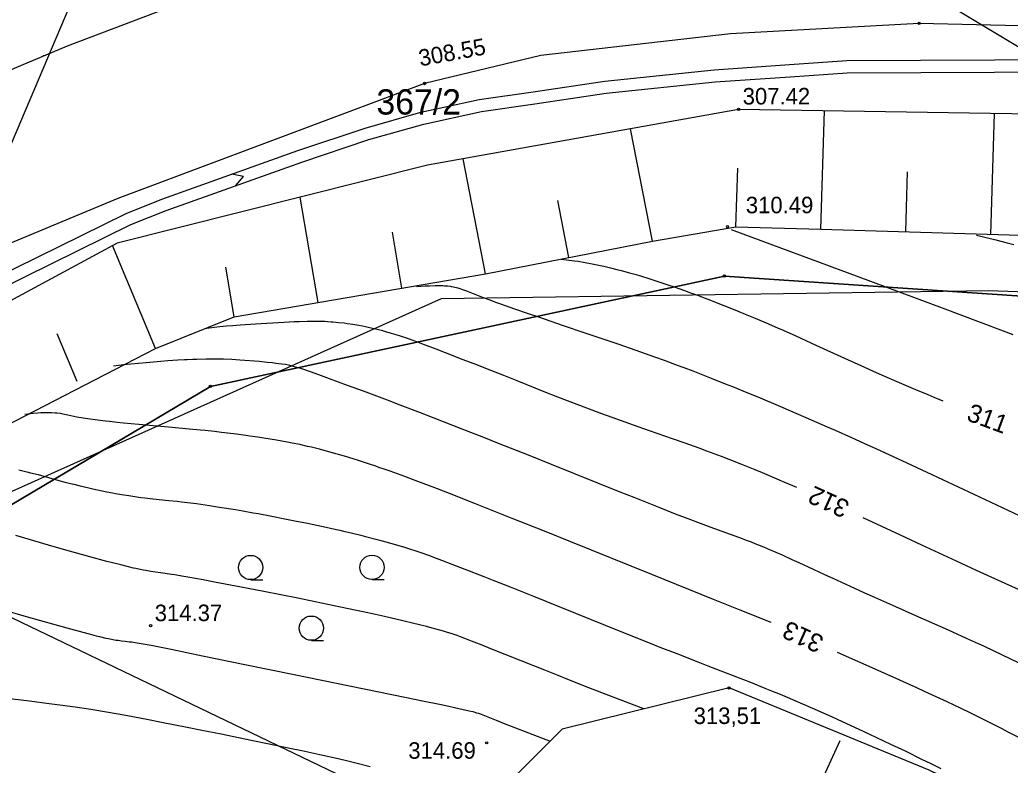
# Model space of a CAD drawing. Extents: x 7477803 to 7478145, y 5500698 to 5500984.
# Drawn here: x 7477904.37 to 7477945.16, y 5500778.77 to 5500809.46 of the extents above; entities that cross this region are included whole.
import ezdxf

# ---------------------------------------------------------------- set-up
doc = ezdxf.new("R2010")
doc.units = 0
for name, color, linetype in [('203-Punkt załamania granicy działki nie stabilizowany', 7, 'Continuous'), ('gr_dzialki', 7, 'Continuous'), ('gr_klasy', 7, 'Continuous'), ('jezdnia', 7, 'Continuous'), ('nr_dzialki', 7, 'Continuous'), ('ogr_symb', 7, 'Continuous'), ('pkt_wys', 7, 'Continuous'), ('rowy', 7, 'Continuous'), ('skarp_wypel', 7, 'Continuous'), ('skarpa_dol', 7, 'Continuous'), ('skarpa_gora', 7, 'Continuous'), ('warst_ciagla', 7, 'Continuous'), ('warst_opis', 7, 'Continuous'), ('warst_pogrub', 7, 'Continuous'), ('warst_przeryw', 7, 'Continuous'), ('zakresy', 7, 'Continuous'), ('zielen', 7, 'Continuous')]:
    doc.layers.add(name, color=color, linetype=linetype)

# ---------------------------------------------------------------- blocks, each defined once
blk = doc.blocks.new('203')
blk.add_circle((0, 0), 0.045)
blk = doc.blocks.new('801')
at = {"layer": 'pkt_wys'}
blk.add_circle((0, 0), 0.045, dxfattribs=at)
blk.add_circle((0, 0), 0.045, dxfattribs=at)
blk = doc.blocks.new('941_5')
at = {"layer": 'zielen'}
for p, q in [((-2.5, 0.46), (-2, 0.46)), ((2.5, 0.46), (3, 0.46)), ((0, -2.04), (0.5, -2.04))]:
    blk.add_line(p, q, dxfattribs=at)
for centre in [(-2.503, 0.963), (2.497, 0.963), (-0.003, -1.537)]:
    blk.add_circle(centre, 0.5, dxfattribs=at)
blk = doc.blocks.new('801_5_1')
at = {"layer": 'pkt_wys'}
blk.add_circle((0, 0), 0.05, dxfattribs=at)
blk.add_circle((0, 0), 0.05, dxfattribs=at)
blk = doc.blocks.new('801_5_3')
at = {"layer": 'pkt_wys'}
blk.add_circle((0, 0), 0.05, dxfattribs=at)
blk.add_circle((0, 0), 0.05, dxfattribs=at)

msp = doc.modelspace()

# ---------------------------------------------------------------- linework, layer by layer
at = {"layer": 'gr_dzialki'}
for points in [[(7477906.59, 5500810.42), (7477901.18, 5500797.68)], [(7477942.51, 5500810.15), (7477965.87, 5500796.14)], [(7477912.22, 5500794.37), (7477933.39, 5500798.91)], [(7477933.39, 5500798.91), (7477948.7, 5500797.88)], [(7477898.04, 5500785.95), (7477912.22, 5500794.37)]]:
    msp.add_lwpolyline(points, dxfattribs=at)
at = {"layer": 'gr_klasy'}
for points in [[(7477933.39, 5500798.91), (7477912.22, 5500794.37)], [(7477948.7, 5500797.88), (7477933.39, 5500798.91)], [(7477912.22, 5500794.37), (7477898.04, 5500785.95)]]:
    msp.add_lwpolyline(points, dxfattribs=at)
at = {"layer": 'jezdnia'}
for points in [[(7477875.926, 5500787.879), (7477876.814, 5500788.851), (7477888.353, 5500798.574), (7477893.52, 5500801.94), (7477899.965, 5500805.717), (7477906.333, 5500808.394), (7477918.837, 5500813.137), (7477925.266, 5500814.534), (7477933.655, 5500815.503), (7477941.064, 5500815.881), (7477951.515, 5500815.693), (7477966.065, 5500814.879), (7477981.427, 5500813.916), (7477996.758, 5500812.562), (7478008.149, 5500811.845)], [(7478007.787, 5500804.444), (7477996.226, 5500805.272), (7477980.454, 5500806.765), (7477965.783, 5500808.078), (7477950.842, 5500809.092), (7477941.412, 5500809.312), (7477933.642, 5500808.883), (7477925.833, 5500807.985), (7477921.044, 5500806.84), (7477908.409, 5500802.106), (7477902.302, 5500799.559), (7477897.005, 5500796.683), (7477891.579, 5500793.077), (7477886.813, 5500789.372), (7477881.349, 5500784.496), (7477881.326, 5500784.471)]]:
    msp.add_lwpolyline(points, dxfattribs=at)
at = {"layer": 'ogr_symb'}
msp.add_lwpolyline([(7477891.276, 5500779.392), (7477896.666, 5500786.743), (7477921.734, 5500797.99), (7477944.284, 5500798.315), (7477964.224, 5500797.617), (7478003.756, 5500796.28)], dxfattribs=at)
at = {"layer": 'rowy'}
for points in [[(7477903.253, 5500798.785), (7477908.747, 5500801.483), (7477910.219, 5500802.081), (7477915.822, 5500804.075), (7477918.6, 5500805.006), (7477920.886, 5500805.655), (7477923.298, 5500806.18), (7477925.514, 5500806.496), (7477928.461, 5500806.935), (7477932.972, 5500807.407), (7477936.072, 5500807.618), (7477938.432, 5500807.783), (7477947.546, 5500807.824), (7477950.631, 5500807.793), (7477969.517, 5500806.584), (7477989.191, 5500804.994), (7477997.207, 5500804.282)], [(7477882.663, 5500783.628), (7477883.714, 5500784.691), (7477887.616, 5500787.993), (7477891.069, 5500790.733), (7477893.37, 5500792.367), (7477898.157, 5500795.46), (7477901.645, 5500797.349), (7477903.482, 5500798.34), (7477908.951, 5500801.027), (7477910.397, 5500801.613), (7477915.985, 5500803.602), (7477918.748, 5500804.528), (7477921.007, 5500805.169), (7477923.387, 5500805.687), (7477925.587, 5500806.001), (7477928.524, 5500806.439), (7477933.015, 5500806.909), (7477936.106, 5500807.119), (7477938.45, 5500807.283), (7477947.545, 5500807.324), (7477950.612, 5500807.294), (7477969.481, 5500806.086), (7477989.149, 5500804.495), (7477997.163, 5500803.784)], [(7477913.272, 5500802.637), (7477913.579, 5500803.004), (7477913.105, 5500803.108)]]:
    msp.add_lwpolyline(points, dxfattribs=at)
at = {"layer": 'skarp_wypel'}
for p, q in [((7477937.366, 5500800.835), (7477937.511, 5500805.721)), ((7477944.363, 5500800.628), (7477944.51, 5500805.608)), ((7477930.426, 5500800.345), (7477929.523, 5500804.978)), ((7477923.556, 5500799.006), (7477922.633, 5500803.739)), ((7477933.868, 5500800.938), (7477933.939, 5500803.358)), ((7477940.865, 5500800.731), (7477940.938, 5500803.198)), ((7477916.657, 5500797.823), (7477915.92, 5500802.16)), ((7477926.991, 5500799.675), (7477926.535, 5500802.017)), ((7477920.107, 5500798.409), (7477919.716, 5500800.711)), ((7477909.966, 5500795.925), (7477908.188, 5500800.168)), ((7477913.206, 5500797.237), (7477912.86, 5500799.272)), ((7477906.738, 5500794.573), (7477905.915, 5500796.536)), ((7477935.1, 5500773.056), (7477938.156, 5500779.794))]:
    msp.add_line(p, q, dxfattribs=at)
at = {"layer": 'skarpa_dol'}
msp.add_lwpolyline([(7478003.179, 5500722.859), (7478004.323, 5500725.251), (7478005.298, 5500730.032), (7478003.066, 5500732.439), (7477998.881, 5500736.525), (7477989.029, 5500747.324), (7477982.233, 5500752.776), (7477973.187, 5500758.837), (7477956.935, 5500769.599), (7477950.58, 5500774.332), (7477941.825, 5500778.562), (7477933.581, 5500781.953), (7477926.713, 5500780.256), (7477921.899, 5500775.451), (7477920.234, 5500772.903)], dxfattribs=at)
at = {"layer": 'skarpa_gora'}
for points in [[(7478007.749, 5500802.055), (7477980.618, 5500803.745), (7477949.546, 5500805.521), (7477933.975, 5500805.774), (7477921.168, 5500803.47), (7477908.381, 5500800.266), (7477897.978, 5500794.654), (7477888.325, 5500787.474), (7477883.93, 5500782.828)], [(7477889.282, 5500779.695), (7477895.338, 5500786.582), (7477897.871, 5500788.956), (7477903.767, 5500792.731), (7477909.966, 5500795.925), (7477913.206, 5500797.237), (7477923.556, 5500799.006), (7477930.426, 5500800.345), (7477933.868, 5500800.938), (7477937.366, 5500800.835), (7477947.862, 5500800.525), (7477951.313, 5500800.09), (7477958.091, 5500798.34), (7477959.924, 5500797.862), (7477975.395, 5500787.769), (7477983.174, 5500779.337)]]:
    msp.add_lwpolyline(points, dxfattribs=at)
at = {"layer": 'warst_ciagla'}
for points in [[(7477905.377, 5500807.994), (7477905.336, 5500807.972)], [(7477926.665, 5500799.612), (7477927, 5500799.571), (7477927.221, 5500799.54), (7477927.368, 5500799.517), (7477927.658, 5500799.468), (7477927.872, 5500799.428), (7477928.014, 5500799.4), (7477928.294, 5500799.341), (7477928.431, 5500799.311), (7477928.703, 5500799.247), (7477928.968, 5500799.182), (7477929.142, 5500799.137), (7477929.479, 5500799.046), (7477929.754, 5500798.969), (7477929.932, 5500798.917), (7477930.279, 5500798.812), (7477930.448, 5500798.759), (7477930.78, 5500798.651), (7477931.107, 5500798.542), (7477931.322, 5500798.467), (7477931.752, 5500798.314), (7477931.995, 5500798.226), (7477932.321, 5500798.105), (7477932.485, 5500798.043), (7477932.815, 5500797.918), (7477933.259, 5500797.745), (7477933.482, 5500797.657), (7477933.99, 5500797.453), (7477934.245, 5500797.348), (7477934.588, 5500797.205), (7477934.761, 5500797.132), (7477935.107, 5500796.985), (7477935.573, 5500796.783), (7477935.808, 5500796.68), (7477936.34, 5500796.443), (7477937.156, 5500796.071), (7477938.342, 5500795.528), (7477939.007, 5500795.228), (7477939.647, 5500794.942), (7477939.981, 5500794.795), (7477940.492, 5500794.573), (7477941.265, 5500794.242), (7477941.773, 5500794.03), (7477942.022, 5500793.927), (7477942.385, 5500793.78)], [(7477936.377, 5500790.203), (7477935.882, 5500790.417), (7477935.564, 5500790.553), (7477934.955, 5500790.807), (7477934.665, 5500790.927), (7477934.111, 5500791.15), (7477933.593, 5500791.354), (7477933.268, 5500791.479), (7477932.664, 5500791.707), (7477932.351, 5500791.823), (7477931.776, 5500792.031), (7477931.254, 5500792.214), (7477930.312, 5500792.539), (7477929.641, 5500792.773), (7477928.772, 5500793.082), (7477928.349, 5500793.236), (7477927.728, 5500793.466), (7477926.927, 5500793.77), (7477926.538, 5500793.92), (7477925.968, 5500794.146), (7477924.855, 5500794.592), (7477924.301, 5500794.812), (7477923.563, 5500795.105), (7477923.193, 5500795.25), (7477922.638, 5500795.467), (7477921.898, 5500795.753), (7477921.527, 5500795.896), (7477921.033, 5500796.084), (7477920.786, 5500796.176), (7477920.417, 5500796.308), (7477920.05, 5500796.433), (7477919.867, 5500796.491), (7477919.686, 5500796.547), (7477919.444, 5500796.616), (7477919.324, 5500796.649), (7477919.085, 5500796.711), (7477918.768, 5500796.785), (7477918.61, 5500796.819), (7477918.492, 5500796.842), (7477918.335, 5500796.872), (7477918.257, 5500796.886), (7477918.082, 5500796.915), (7477917.85, 5500796.949), (7477917.734, 5500796.964), (7477917.504, 5500796.99), (7477917.402, 5500797), (7477917.266, 5500797.012), (7477917.199, 5500797.017), (7477917.047, 5500797.027), (7477916.934, 5500797.033), (7477916.783, 5500797.039), (7477916.708, 5500797.041), (7477916.539, 5500797.043), (7477916.428, 5500797.044), (7477916.206, 5500797.041), (7477915.88, 5500797.031), (7477915.668, 5500797.021), (7477915.26, 5500796.999), (7477914.076, 5500796.928), (7477913.443, 5500796.886), (7477913.151, 5500796.865), (7477912.887, 5500796.844), (7477912.741, 5500796.83), (7477912.487, 5500796.804), (7477912.173, 5500796.766), (7477911.988, 5500796.742)], [(7477935.315, 5500784.644), (7477934.996, 5500784.776), (7477934.428, 5500785.001), (7477934.043, 5500785.154), (7477932.945, 5500785.594), (7477930.408, 5500786.618), (7477927.066, 5500787.968), (7477925.988, 5500788.401), (7477924.652, 5500788.934), (7477924.027, 5500789.182), (7477923.143, 5500789.531), (7477922.065, 5500789.953), (7477921.569, 5500790.145), (7477920.657, 5500790.494), (7477920.233, 5500790.653), (7477919.624, 5500790.874), (7477919.426, 5500790.944), (7477919.165, 5500791.035), (7477919.037, 5500791.079), (7477918.781, 5500791.165), (7477918.447, 5500791.274), (7477918.282, 5500791.327), (7477917.918, 5500791.44), (7477917.739, 5500791.494), (7477917.503, 5500791.563), (7477917.387, 5500791.597), (7477917.157, 5500791.661), (7477916.857, 5500791.742), (7477916.709, 5500791.78), (7477916.382, 5500791.861), (7477916.222, 5500791.899), (7477915.905, 5500791.97), (7477915.589, 5500792.035), (7477915.377, 5500792.077), (7477914.941, 5500792.155), (7477914.422, 5500792.24), (7477914.181, 5500792.277), (7477913.851, 5500792.324), (7477913.681, 5500792.347), (7477913.29, 5500792.399), (7477912.676, 5500792.473), (7477912.393, 5500792.504), (7477912.006, 5500792.545), (7477911.809, 5500792.566), (7477911.354, 5500792.61), (7477910.65, 5500792.673), (7477909.714, 5500792.754), (7477909.268, 5500792.794), (7477908.645, 5500792.855), (7477908.386, 5500792.882), (7477908.06, 5500792.918), (7477907.905, 5500792.936), (7477907.574, 5500792.977), (7477907.172, 5500793.032), (7477906.986, 5500793.061), (7477906.723, 5500793.105), (7477906.475, 5500793.153), (7477906.355, 5500793.179), (7477906.144, 5500793.226), (7477906.029, 5500793.247), (7477905.902, 5500793.264), (7477905.833, 5500793.271), (7477905.679, 5500793.281), (7477905.594, 5500793.284), (7477905.453, 5500793.283), (7477905.239, 5500793.275), (7477905.119, 5500793.267), (7477904.922, 5500793.25), (7477904.703, 5500793.226), (7477904.584, 5500793.212)], [(7477946.2, 5500785.693), (7477944.962, 5500786.248), (7477944.224, 5500786.583), (7477943.772, 5500786.79), (7477942.951, 5500787.169), (7477941.526, 5500787.831), (7477940.651, 5500788.239), (7477939.109, 5500788.962)], [(7477930.075, 5500781.087), (7477928.528, 5500781.682), (7477927.809, 5500781.961), (7477926.938, 5500782.303), (7477926.541, 5500782.46), (7477925.99, 5500782.68), (7477925.017, 5500783.071), (7477923.777, 5500783.567), (7477923.416, 5500783.709), (7477922.976, 5500783.882), (7477922.773, 5500783.96), (7477922.516, 5500784.058), (7477922.387, 5500784.105), (7477922.18, 5500784.177), (7477921.947, 5500784.251), (7477921.817, 5500784.29), (7477921.677, 5500784.331), (7477921.472, 5500784.388), (7477921.362, 5500784.417), (7477921.128, 5500784.479), (7477920.784, 5500784.565), (7477920.599, 5500784.61), (7477920.151, 5500784.717), (7477919.396, 5500784.89), (7477919.028, 5500784.971), (7477918.507, 5500785.085), (7477918.233, 5500785.143), (7477917.585, 5500785.28), (7477916.541, 5500785.496), (7477915.823, 5500785.642), (7477914.428, 5500785.921), (7477913.485, 5500786.105), (7477912.392, 5500786.314), (7477911.917, 5500786.403), (7477911.292, 5500786.515), (7477911.049, 5500786.558), (7477910.757, 5500786.607), (7477910.625, 5500786.628), (7477910.361, 5500786.668), (7477909.764, 5500786.75), (7477909.564, 5500786.784), (7477909.453, 5500786.804), (7477909.33, 5500786.829), (7477909.15, 5500786.868), (7477909.053, 5500786.89), (7477908.843, 5500786.939), (7477908.533, 5500787.015), (7477908.365, 5500787.057), (7477907.954, 5500787.164), (7477907.255, 5500787.353), (7477906.913, 5500787.448), (7477906.425, 5500787.586), (7477906.168, 5500787.659), (7477905.558, 5500787.835), (7477904.212, 5500788.227)], [(7477945.597, 5500779.871), (7477945.081, 5500780.137), (7477944.826, 5500780.267), (7477944.259, 5500780.552), (7477943.514, 5500780.921), (7477943.138, 5500781.104), (7477942.561, 5500781.379), (7477941.956, 5500781.661), (7477941.639, 5500781.806), (7477941.311, 5500781.956), (7477940.614, 5500782.269), (7477939.847, 5500782.61), (7477938.048, 5500783.407)]]:
    msp.add_lwpolyline(points, dxfattribs=at)
at = {"layer": 'warst_pogrub'}
for points in [[(7477943.775, 5500800.594), (7477944.569, 5500800.402), (7477945.034, 5500800.285), (7477945.317, 5500800.212)], [(7477903.954, 5500781.515), (7477904.667, 5500781.432), (7477904.976, 5500781.394), (7477905.38, 5500781.344), (7477905.578, 5500781.318), (7477906.017, 5500781.259), (7477906.656, 5500781.169), (7477906.931, 5500781.128), (7477907.291, 5500781.073), (7477907.468, 5500781.045), (7477907.857, 5500780.982), (7477908.426, 5500780.884), (7477908.806, 5500780.815), (7477909.607, 5500780.664), (7477910.274, 5500780.535), (7477911.263, 5500780.341), (7477911.8, 5500780.234), (7477912.659, 5500780.061), (7477913.904, 5500779.808), (7477914.57, 5500779.671), (7477915.5, 5500779.479), (7477915.982, 5500779.377), (7477916.725, 5500779.215), (7477917.488, 5500779.041), (7477917.877, 5500778.949), (7477918.27, 5500778.854), (7477918.8, 5500778.72)]]:
    msp.add_lwpolyline(points, dxfattribs=at)
at = {"layer": 'warst_przeryw'}
for points in [[(7477945.289, 5500796.496), (7477944.893, 5500796.647), (7477943.944, 5500797.005), (7477942.379, 5500797.59), (7477938.941, 5500798.864), (7477933.686, 5500800.81)], [(7477946.947, 5500788.378), (7477943.677, 5500789.913), (7477941.739, 5500790.821), (7477940.708, 5500791.301), (7477939.668, 5500791.779), (7477939.152, 5500792.015), (7477938.642, 5500792.245), (7477937.971, 5500792.545), (7477937.639, 5500792.692), (7477936.985, 5500792.98), (7477936.131, 5500793.349), (7477935.711, 5500793.529), (7477934.784, 5500793.918), (7477934.33, 5500794.105), (7477933.735, 5500794.348), (7477933.442, 5500794.466), (7477932.863, 5500794.695), (7477932.109, 5500794.988), (7477931.74, 5500795.129), (7477931.466, 5500795.232), (7477931.105, 5500795.366), (7477930.927, 5500795.431), (7477930.53, 5500795.575), (7477929.758, 5500795.85), (7477929.019, 5500796.106), (7477927.662, 5500796.565), (7477926.769, 5500796.867), (7477925.752, 5500797.212), (7477925.317, 5500797.361), (7477924.758, 5500797.553), (7477924.185, 5500797.752), (7477923.973, 5500797.828), (7477923.742, 5500797.912), (7477923.464, 5500798.02), (7477923.121, 5500798.156), (7477922.778, 5500798.289), (7477922.624, 5500798.347), (7477922.545, 5500798.374), (7477922.422, 5500798.412), (7477922.291, 5500798.443), (7477922.231, 5500798.455), (7477922.148, 5500798.47), (7477922.105, 5500798.476), (7477922.007, 5500798.488), (7477921.87, 5500798.501), (7477921.797, 5500798.505), (7477921.679, 5500798.509), (7477921.478, 5500798.509), (7477921.242, 5500798.501), (7477921.071, 5500798.492), (7477920.716, 5500798.469)], [(7477945.526, 5500782.976), (7477944.823, 5500783.315), (7477944.505, 5500783.466), (7477944.077, 5500783.666), (7477943.86, 5500783.767), (7477943.368, 5500783.992), (7477942.62, 5500784.329), (7477941.146, 5500784.982), (7477940.453, 5500785.29), (7477939.585, 5500785.677), (7477939.175, 5500785.861), (7477938.591, 5500786.126), (7477937.869, 5500786.455), (7477937.532, 5500786.61), (7477937.056, 5500786.831), (7477936.467, 5500787.104), (7477936.187, 5500787.232), (7477935.781, 5500787.414), (7477935.264, 5500787.638), (7477935.016, 5500787.742), (7477934.657, 5500787.889), (7477934.503, 5500787.95), (7477934.302, 5500788.029), (7477934.204, 5500788.066), (7477933.987, 5500788.147), (7477932.962, 5500788.512), (7477932.512, 5500788.679), (7477931.792, 5500788.952), (7477931.38, 5500789.112), (7477930.699, 5500789.379), (7477929.669, 5500789.787), (7477929.103, 5500790.013), (7477926.276, 5500791.151), (7477925.325, 5500791.531), (7477924.089, 5500792.022), (7477923.484, 5500792.261), (7477922.593, 5500792.61), (7477921.437, 5500793.059), (7477920.872, 5500793.276), (7477920.044, 5500793.593), (7477919.514, 5500793.795), (7477918.528, 5500794.166), (7477917.874, 5500794.41), (7477917.124, 5500794.685), (7477916.801, 5500794.802), (7477916.383, 5500794.95), (7477915.946, 5500795.099), (7477915.781, 5500795.152), (7477915.592, 5500795.206), (7477915.492, 5500795.231), (7477915.432, 5500795.243), (7477915.312, 5500795.264), (7477915.16, 5500795.286), (7477914.92, 5500795.316), (7477914.784, 5500795.332), (7477914.56, 5500795.355), (7477914.225, 5500795.388), (7477914.042, 5500795.404), (7477913.646, 5500795.437), (7477913.435, 5500795.452), (7477913.105, 5500795.47), (7477912.764, 5500795.482), (7477912.608, 5500795.486), (7477912.397, 5500795.488), (7477912.29, 5500795.488), (7477912.046, 5500795.487), (7477911.669, 5500795.479), (7477911.498, 5500795.474), (7477911.267, 5500795.464), (7477911.149, 5500795.459), (7477910.882, 5500795.444), (7477910.469, 5500795.416), (7477910.185, 5500795.394), (7477909.583, 5500795.343), (7477908.944, 5500795.282), (7477908.636, 5500795.251), (7477908.226, 5500795.205)], [(7477904.338, 5500790.926), (7477904.662, 5500790.851), (7477904.818, 5500790.812), (7477905.123, 5500790.734), (7477905.983, 5500790.499), (7477906.19, 5500790.444), (7477906.463, 5500790.373), (7477906.597, 5500790.339), (7477906.864, 5500790.273), (7477907.213, 5500790.191), (7477907.384, 5500790.152), (7477907.764, 5500790.07), (7477907.951, 5500790.033), (7477908.196, 5500789.985), (7477908.317, 5500789.963), (7477908.556, 5500789.92), (7477908.868, 5500789.869), (7477909.022, 5500789.846), (7477909.36, 5500789.799), (7477909.526, 5500789.779), (7477909.854, 5500789.742), (7477910.514, 5500789.675), (7477910.858, 5500789.639), (7477911.035, 5500789.619), (7477911.278, 5500789.589), (7477911.402, 5500789.573), (7477911.656, 5500789.54), (7477912.006, 5500789.491), (7477912.186, 5500789.464), (7477912.603, 5500789.401), (7477913.26, 5500789.294), (7477913.563, 5500789.242), (7477913.98, 5500789.168), (7477914.193, 5500789.129), (7477914.684, 5500789.038), (7477915.362, 5500788.907), (7477915.706, 5500788.838), (7477916.223, 5500788.733), (7477916.983, 5500788.571), (7477917.229, 5500788.516), (7477917.55, 5500788.444), (7477917.708, 5500788.407), (7477918.017, 5500788.334), (7477918.416, 5500788.237), (7477918.61, 5500788.188), (7477919.035, 5500788.079), (7477919.24, 5500788.024), (7477919.507, 5500787.95), (7477919.637, 5500787.914), (7477919.892, 5500787.84), (7477920.219, 5500787.742), (7477920.378, 5500787.693), (7477920.721, 5500787.582), (7477920.886, 5500787.527), (7477921.207, 5500787.415), (7477921.522, 5500787.3), (7477921.734, 5500787.22), (7477922.171, 5500787.053), (7477922.703, 5500786.846), (7477923.482, 5500786.541), (7477923.902, 5500786.375), (7477924.57, 5500786.109), (7477925.531, 5500785.725), (7477926.042, 5500785.52), (7477928.475, 5500784.539), (7477929.26, 5500784.224), (7477930.259, 5500783.827), (7477930.737, 5500783.638), (7477931.427, 5500783.367), (7477932.298, 5500783.028), (7477932.712, 5500782.868), (7477933.89, 5500782.415), (7477934.47, 5500782.188), (7477935.062, 5500781.95), (7477935.33, 5500781.84), (7477935.692, 5500781.69), (7477935.875, 5500781.613), (7477936.291, 5500781.436), (7477936.928, 5500781.16), (7477937.216, 5500781.033), (7477937.605, 5500780.861), (7477937.801, 5500780.773), (7477938.247, 5500780.57), (7477938.925, 5500780.259), (7477939.374, 5500780.049), (7477940.237, 5500779.642), (7477940.83, 5500779.358), (7477941.542, 5500779.011), (7477941.864, 5500778.851), (7477942.303, 5500778.63)], [(7477903.598, 5500785.201), (7477904.628, 5500784.9), (7477905.808, 5500784.563), (7477906.315, 5500784.421), (7477906.971, 5500784.243), (7477907.223, 5500784.177), (7477907.52, 5500784.101), (7477907.652, 5500784.068), (7477907.91, 5500784.008), (7477908.018, 5500783.984), (7477908.198, 5500783.949), (7477908.341, 5500783.925), (7477908.421, 5500783.914), (7477908.561, 5500783.898), (7477908.708, 5500783.881), (7477908.896, 5500783.857), (7477908.987, 5500783.845), (7477909.118, 5500783.826), (7477909.286, 5500783.801), (7477909.366, 5500783.788), (7477909.62, 5500783.742), (7477909.788, 5500783.71), (7477910.604, 5500783.545), (7477911.902, 5500783.279), (7477913.644, 5500782.919), (7477915.671, 5500782.503), (7477917.944, 5500782.041), (7477920.294, 5500781.564), (7477920.963, 5500781.427), (7477921.722, 5500781.268), (7477922.044, 5500781.199), (7477922.457, 5500781.109), (7477922.874, 5500781.013), (7477923.025, 5500780.976), (7477923.186, 5500780.932), (7477923.261, 5500780.909), (7477923.375, 5500780.868), (7477923.651, 5500780.759), (7477923.993, 5500780.623), (7477924.318, 5500780.493), (7477924.607, 5500780.381), (7477926.22, 5500779.763)]]:
    msp.add_lwpolyline(points, dxfattribs=at)
at = {"layer": 'zakresy'}
msp.add_lwpolyline([(7477995.059, 5500962.348), (7477983.951, 5500968.084), (7477970.781, 5500968.613), (7477936.09, 5500958.171), (7477930.511, 5500954.336), (7477914.305, 5500958.58), (7477904.32, 5500957.41), (7477897.265, 5500950.868), (7477811.424, 5500829.338), (7477936.003, 5500769.492), (7478008.982, 5500726.585), (7478019.402, 5500721.781), (7478037.95, 5500734.97), (7478039.493, 5500755.094), (7478043.98, 5500765.708), (7478067.545, 5500795.068), (7478092.109, 5500820.25), (7478076.156, 5500837.989), (7478068.105, 5500851.146), (7478061.422, 5500873.298), (7478054.135, 5500876.371), (7478039.669, 5500897.644), (7478026.36, 5500915.23), (7478015.054, 5500927.728)], close=True, dxfattribs=at)

# ---------------------------------------------------------------- block references
at = {"layer": '203-Punkt załamania granicy działki nie stabilizowany'}
for p in [(7477933.39, 5500798.91), (7477912.22, 5500794.37)]:
    msp.add_blockref('203', p, dxfattribs=at)
at = {"layer": 'pkt_wys', "rotation": 0.0626175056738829}
for name, p in [('801', (7477941.412, 5500809.312)), ('801_5_1', (7477921.044, 5500806.84)), ('801', (7477933.975, 5500805.774)), ('801', (7477933.521, 5500800.943)), ('801', (7477909.759, 5500784.517)), ('801_5_3', (7477933.581, 5500781.953)), ('801', (7477923.604, 5500779.692))]:
    msp.add_blockref(name, p, dxfattribs=at)
at = {"layer": 'zielen', "rotation": 0.0626175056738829}
msp.add_blockref('941_5', (7477916.381, 5500785.951), dxfattribs=at)

# ---------------------------------------------------------------- texts
at = {"layer": 'nr_dzialki'}
msp.add_text('367/2', height=1.04, dxfattribs=at).set_placement((7477919.06, 5500805.56))
at = {"layer": 'pkt_wys'}
for s, rotation, p in [('308.55', 10.3953, (7477920.868, 5500807.54)), ('307.42', 0.0626, (7477934.144, 5500805.974)), ('310.49', 0.0626, (7477934.274, 5500801.494)), ('314.37', 0.0626, (7477909.928, 5500784.702)), ('313,51', 0.0626, (7477932.126, 5500780.467)), ('314.69', 0.0626, (7477920.373, 5500779.036))]:
    msp.add_text(s, height=0.68, rotation=rotation, dxfattribs=at).set_placement(p)
at = {"layer": 'warst_opis'}
for s, rotation, p in [('311', 339.7181, (7477943.323, 5500792.985)), ('312', 155.5738, (7477938.603, 5500789.604)), ('313', 155.6412, (7477937.541, 5500784.048))]:
    msp.add_text(s, height=0.75, rotation=rotation, dxfattribs=at).set_placement(p)

doc.saveas('drawing.dxf')
